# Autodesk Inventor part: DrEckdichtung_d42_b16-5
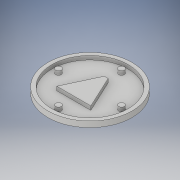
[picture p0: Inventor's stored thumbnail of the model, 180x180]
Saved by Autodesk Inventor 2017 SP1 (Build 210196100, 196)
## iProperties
Part Number: DrEckdichtung_d42_b16-5
Material: Generisch
Document SubType Name: Modeling
Designer: haesner
Density: 1 g/cm^3
Appearance: Vorgabe
Part Number: DrEckdichtung_d42_b16-5_3D-Druck
Author: haesner
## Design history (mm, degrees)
sketch "Skizze1"
  geometry: C1 r 22 at (0, 0); 1 further point
  constraints: 1 centre point, 1 coincident
  dimensions: "d0" = 44 diameter of C1
extrude "Extrusion1" new body sketch "Skizze1" distance "d1" = 3; taper "d2" = 0 deg
sketch "Skizze2"
  geometry: L1 (0, 16.5)-(-16.5, 0); L2 (-16.5, 0)-(0, -16.5); L3 (0, -16.5)-(16.5, 0); L4 (16.5, 0)-(0, 16.5); L5 (-30.8, 0)-(30.8, 0) reference; L6 (0, -30.8)-(0, 30.8) reference; L7 (-1, 8.5)-(1, 8.5); L8 (1, 8.5)-(8.927, -8.5); L9 (8.927, -8.5)-(-8.927, -8.5); L10 (-8.927, -8.5)-(-1, 8.5); C1 r 20 at (0, 0); C2 r 1.5 at (0, 16.5); C3 r 1.5 at (16.5, 0); C4 r 1.5 at (0, -16.5); C5 r 1.5 at (-16.5, 0); 1 further point
  constraints: 16 end point, 5 centre point, 5 coincident, 3 equal radius, 3 parallel, 3 point on line, 2 equal length, 1 horizontal, 1 perpendicular, 1 symmetric about line, 1 other
  dimensions: "d3" = 16.5 distance from line of L1.start L5; "d4" = 40 diameter of C1; "d5" = 3 diameter of C2; "d11" = 17 distance between parallel lines of L9 L7; "d12" = 2 distance of L7.start L7.end; "d13" = 25 deg angle of L6 L8
extrude "Extrusion3" cut sketch "Skizze2" distance "d9" = 2; taper "d10" = 0 deg
node "Volumenkörper1"
